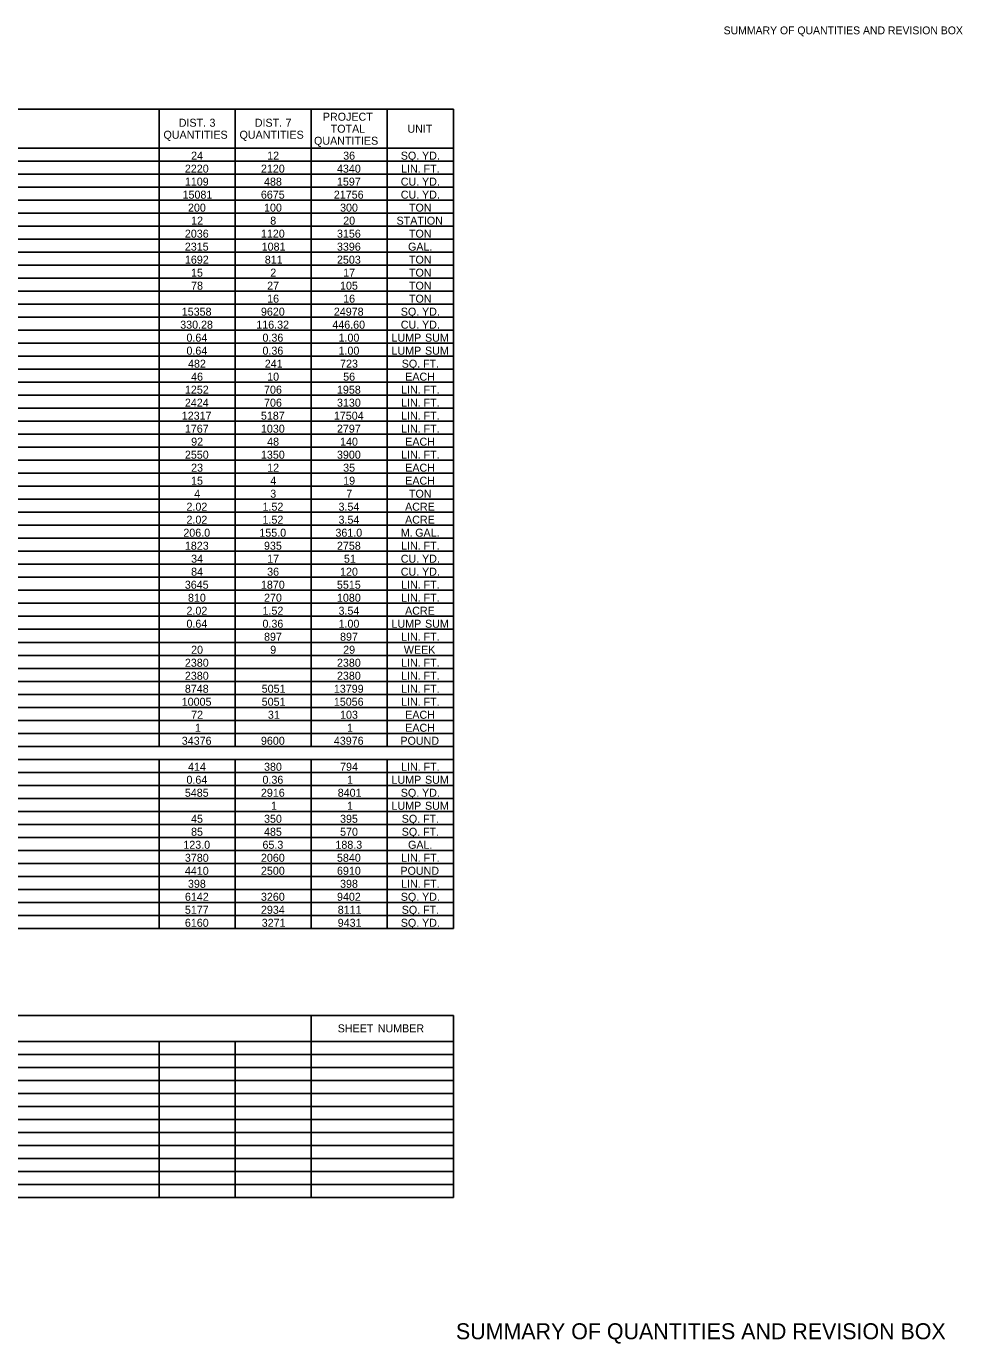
# Model space of a CAD drawing. Extents: x 544478 to 1930787, y -1948294 to 596640.
# Drawn here: x 546965 to 547668, y -1948294 to -1947306 of the extents above; entities that cross this region are included whole.
import ezdxf

# ---------------------------------------------------------------- set-up
doc = ezdxf.new("R2010")
doc.units = 0
for name, color, linetype in [('Default', 7, 'Continuous'), ('R_Border', 7, 'Continuous'), ('R_Border Prem', 7, 'Continuous')]:
    doc.layers.add(name, color=color, linetype=linetype)

msp = doc.modelspace()

# ---------------------------------------------------------------- linework, layer by layer
at = {"layer": 'Default'}
for p, q in [((546495.1, -1947368.6), (547285.83, -1947368.6)), ((547064.99, -1947846.35), (547064.99, -1947368.6)), ((547064.99, -1947719.6), (547064.99, -1947368.6)), ((547122.03, -1947846.35), (547122.03, -1947368.6)), ((547122.03, -1947397.85), (547122.03, -1947368.6)), ((547179.06, -1947846.35), (547179.06, -1947368.6)), ((547236.1, -1947846.35), (547236.1, -1947368.6)), ((547236.1, -1947846.35), (547236.1, -1947368.6)), ((547285.83, -1947982.85), (547285.83, -1947368.6)), ((546495.1, -1947397.85), (547285.83, -1947397.85)), ((546495.1, -1947397.85), (547285.83, -1947397.85)), ((546495.1, -1947407.6), (547285.83, -1947407.6)), ((546495.1, -1947417.35), (547285.83, -1947417.35)), ((546495.1, -1947427.1), (547285.83, -1947427.1)), ((546495.1, -1947436.85), (547285.83, -1947436.85)), ((546495.1, -1947446.6), (547285.83, -1947446.6)), ((546495.1, -1947456.35), (547285.83, -1947456.35)), ((546495.1, -1947466.1), (547285.83, -1947466.1)), ((546495.1, -1947475.85), (547285.83, -1947475.85)), ((546495.1, -1947485.6), (547285.83, -1947485.6)), ((546495.1, -1947495.35), (547285.83, -1947495.35)), ((546495.1, -1947505.1), (547285.83, -1947505.1)), ((546495.1, -1947514.85), (547285.83, -1947514.85)), ((546495.1, -1947524.6), (547285.83, -1947524.6)), ((546495.1, -1947534.35), (547285.83, -1947534.35)), ((546495.1, -1947544.1), (547285.83, -1947544.1)), ((546495.1, -1947553.85), (547285.83, -1947553.85)), ((546495.1, -1947563.6), (547285.83, -1947563.6)), ((546495.1, -1947573.35), (547285.83, -1947573.35)), ((546495.1, -1947583.1), (547285.83, -1947583.1)), ((546495.1, -1947592.85), (547285.83, -1947592.85)), ((546495.1, -1947602.6), (547285.83, -1947602.6)), ((546495.1, -1947612.35), (547285.83, -1947612.35)), ((546495.1, -1947622.1), (547285.83, -1947622.1)), ((546495.1, -1947631.85), (547285.83, -1947631.85)), ((546495.1, -1947641.6), (547285.83, -1947641.6)), ((546495.1, -1947651.35), (547285.83, -1947651.35)), ((546495.1, -1947661.1), (547285.83, -1947661.1)), ((546495.1, -1947670.85), (547285.83, -1947670.85)), ((546495.1, -1947680.6), (547285.83, -1947680.6)), ((546495.1, -1947690.35), (547285.83, -1947690.35)), ((546495.1, -1947700.1), (547285.83, -1947700.1)), ((546495.1, -1947709.85), (547285.83, -1947709.85)), ((546495.1, -1947719.6), (547285.83, -1947719.6)), ((546495.1, -1947729.35), (547285.83, -1947729.35)), ((547064.99, -1947846.35), (547064.99, -1947729.35)), ((547236.1, -1947729.35), (547285.83, -1947729.35)), ((546495.1, -1947739.1), (547285.83, -1947739.1)), ((546495.1, -1947748.85), (547285.83, -1947748.85)), ((546495.1, -1947758.6), (547285.83, -1947758.6)), ((546495.1, -1947768.35), (547285.83, -1947768.35)), ((546495.1, -1947778.1), (547285.83, -1947778.1)), ((546977.24, -1947778.1), (547064.99, -1947778.1)), ((547064.99, -1947778.1), (547285.83, -1947778.1)), ((546495.1, -1947787.85), (547285.83, -1947787.85)), ((546495.1, -1947797.6), (547285.83, -1947797.6)), ((546495.1, -1947807.35), (547285.83, -1947807.35)), ((546495.1, -1947817.1), (547285.83, -1947817.1)), ((546495.1, -1947826.85), (547285.83, -1947826.85)), ((546495.1, -1947836.6), (547285.83, -1947836.6)), ((546495.1, -1947846.35), (547285.83, -1947846.35)), ((546495.1, -1947846.35), (547285.83, -1947846.35)), ((546495.1, -1947856.1), (547285.83, -1947856.1)), ((546495.1, -1947856.1), (547122.03, -1947856.1)), ((547064.99, -1947982.85), (547064.99, -1947856.1)), ((547064.99, -1947982.85), (547064.99, -1947856.1)), ((547122.03, -1947982.85), (547122.03, -1947856.1)), ((547179.06, -1947856.1), (547285.83, -1947856.1)), ((547179.06, -1947982.85), (547179.06, -1947856.1)), ((547236.1, -1947982.85), (547236.1, -1947856.1)), ((547236.1, -1947982.85), (547236.1, -1947856.1)), ((546495.1, -1947865.85), (547285.83, -1947865.85)), ((546495.1, -1947875.6), (547285.83, -1947875.6)), ((546495.1, -1947885.35), (547285.83, -1947885.35)), ((546495.1, -1947895.1), (547285.83, -1947895.1)), ((546495.1, -1947904.85), (547285.83, -1947904.85)), ((546495.1, -1947914.6), (547285.83, -1947914.6)), ((546495.1, -1947924.35), (547285.83, -1947924.35)), ((546495.1, -1947934.1), (547285.83, -1947934.1)), ((546495.1, -1947943.85), (547285.83, -1947943.85)), ((546495.1, -1947953.6), (547285.83, -1947953.6)), ((546977.24, -1947953.6), (547064.99, -1947953.6)), ((547064.99, -1947953.6), (547285.83, -1947953.6)), ((546495.1, -1947963.35), (547285.83, -1947963.35)), ((546977.24, -1947963.35), (547064.99, -1947963.35)), ((547064.99, -1947963.35), (547285.83, -1947963.35)), ((546495.1, -1947973.1), (547285.83, -1947973.1)), ((546977.24, -1947973.1), (547064.99, -1947973.1)), ((547064.99, -1947973.1), (547285.83, -1947973.1)), ((546495.1, -1947982.85), (547285.83, -1947982.85)), ((546495.1, -1948048.06), (547285.83, -1948048.06)), ((547064.99, -1948048.06), (547285.83, -1948048.06)), ((547179.06, -1948067.56), (547179.06, -1948048.06)), ((547179.06, -1948184.56), (547179.06, -1948048.06)), ((547285.83, -1948184.56), (547285.83, -1948048.06)), ((546495.1, -1948067.56), (547285.83, -1948067.56)), ((547064.99, -1948184.56), (547064.99, -1948067.56)), ((547122.03, -1948184.56), (547122.03, -1948067.56)), ((547179.06, -1948067.56), (547285.83, -1948067.56)), ((546495.1, -1948077.31), (547285.83, -1948077.31)), ((546495.1, -1948087.06), (547285.83, -1948087.06)), ((546495.1, -1948096.81), (547285.83, -1948096.81)), ((546495.1, -1948106.56), (547285.83, -1948106.56)), ((546495.1, -1948116.31), (547285.83, -1948116.31)), ((546495.1, -1948126.06), (547285.83, -1948126.06)), ((546495.1, -1948135.81), (547285.83, -1948135.81)), ((546495.1, -1948145.56), (547285.83, -1948145.56)), ((546495.1, -1948155.31), (547285.83, -1948155.31)), ((546495.1, -1948165.06), (547285.83, -1948165.06)), ((546495.1, -1948174.81), (547285.83, -1948174.81)), ((546495.1, -1948184.56), (547285.83, -1948184.56))]:
    msp.add_line(p, q, dxfattribs=at)

# ---------------------------------------------------------------- texts
for s, p in [('DIST.', (547079.77, -1947381.72)), (' 3', (547100.62, -1947381.72)), ('DIST.', (547136.81, -1947381.72)), (' 7', (547157.66, -1947381.72)), ('PROJECT', (547187.87, -1947377.22)), ('QUANTITIES', (547068.33, -1947390.72)), ('QUANTITIES', (547125.37, -1947390.72)), ('TOTAL', (547193.74, -1947386.22)), ('UNIT', (547251.27, -1947386.22)), ('QUANTITIES', (547181.24, -1947395.22)), ('24', (547089.05, -1947406.4)), ('12', (547146.11, -1947406.4)), ('36', (547203.11, -1947406.4)), ('SQ.', (547246.32, -1947406.4)), (' YD.', (547260.03, -1947406.4)), ('2220', (547084.39, -1947416.15)), ('2120', (547141.43, -1947416.15)), ('4340', (547198.46, -1947416.15)), ('LIN.', (547246.56, -1947416.15)), (' FT.', (547261.2, -1947416.15)), ('1109', (547084.37, -1947425.9)), ('488', (547143.74, -1947425.9)), ('1597', (547198.45, -1947425.9)), ('CU.', (547246.33, -1947425.9)), (' YD.', (547260.03, -1947425.9)), ('15081', (547082.63, -1947435.65)), ('6675', (547141.39, -1947435.65)), ('21756', (547196.12, -1947435.65)), ('CU.', (547246.33, -1947435.65)), (' YD.', (547260.03, -1947435.65)), ('200', (547086.72, -1947445.4)), ('100', (547143.76, -1947445.4)), ('300', (547200.79, -1947445.4)), ('TON', (547252.46, -1947445.4)), ('12', (547089.07, -1947455.15)), ('8', (547148.4, -1947455.15)), ('20', (547203.12, -1947455.15)), ('STATION', (547243.14, -1947455.15)), ('2036', (547084.38, -1947464.9)), ('1120', (547141.43, -1947464.9)), ('3156', (547198.45, -1947464.9)), ('TON', (547252.46, -1947464.9)), ('2315', (547084.35, -1947474.65)), ('1081', (547142, -1947474.65)), ('3396', (547198.45, -1947474.65)), ('GAL.', (547251.78, -1947474.65)), ('1692', (547084.41, -1947484.4)), ('811', (547144.33, -1947484.4)), ('2503', (547198.45, -1947484.4)), ('TON', (547252.46, -1947484.4)), ('15', (547089.01, -1947494.15)), ('2', (547148.44, -1947494.15)), ('17', (547203.11, -1947494.15)), ('TON', (547252.46, -1947494.15)), ('78', (547089.03, -1947503.9)), ('27', (547146.08, -1947503.9)), ('105', (547200.76, -1947503.9)), ('TON', (547252.46, -1947503.9)), ('16', (547146.08, -1947513.65)), ('16', (547203.11, -1947513.65)), ('TON', (547252.46, -1947513.65)), ('15358', (547082.04, -1947523.4)), ('9620', (547141.43, -1947523.4)), ('24978', (547196.12, -1947523.4)), ('SQ.', (547246.32, -1947523.4)), (' YD.', (547260.03, -1947523.4)), ('330.28', (547080.88, -1947533.15)), ('116.32', (547137.95, -1947533.15)), ('446.60', (547194.97, -1947533.15)), ('CU.', (547246.33, -1947533.15)), (' YD.', (547260.03, -1947533.15)), ('0.64', (547085.56, -1947542.9)), ('0.36', (547142.58, -1947542.9)), ('1.00', (547199.63, -1947542.9)), ('LUMP', (547239.34, -1947542.9)), (' SUM', (547262.26, -1947542.9)), ('0.64', (547085.56, -1947552.65)), ('0.36', (547142.58, -1947552.65)), ('1.00', (547199.63, -1947552.65)), ('LUMP', (547239.34, -1947552.65)), (' SUM', (547262.26, -1947552.65)), ('482', (547086.74, -1947562.4)), ('241', (547144.33, -1947562.4)), ('723', (547200.78, -1947562.4)), ('SQ.', (547247.03, -1947562.4)), (' FT.', (547260.74, -1947562.4)), ('1252', (547084.41, -1947581.9)), ('46', (547089.04, -1947572.15)), ('706', (547143.75, -1947581.9)), ('10', (547146.09, -1947572.15)), ('1958', (547198.45, -1947581.9)), ('56', (547203.11, -1947572.15)), ('EACH', (547249.65, -1947572.15)), ('2424', (547084.39, -1947591.65)), ('706', (547143.75, -1947591.65)), ('3130', (547198.46, -1947591.65)), ('LIN.', (547246.56, -1947581.9)), ('LIN.', (547246.56, -1947591.65)), (' FT.', (547261.2, -1947581.9)), (' FT.', (547261.2, -1947591.65)), ('12317', (547082.05, -1947601.4)), ('5187', (547141.42, -1947601.4)), ('17504', (547196.14, -1947601.4)), ('LIN.', (547246.56, -1947601.4)), (' FT.', (547261.2, -1947601.4)), ('1767', (547084.38, -1947611.15)), ('1030', (547141.43, -1947611.15)), ('2797', (547198.45, -1947611.15)), ('LIN.', (547246.56, -1947611.15)), (' FT.', (547261.2, -1947611.15)), ('92', (547089.07, -1947620.9)), ('48', (547146.07, -1947620.9)), ('140', (547200.79, -1947620.9)), ('EACH', (547249.65, -1947620.9)), ('2550', (547084.39, -1947630.65)), ('1350', (547141.43, -1947630.65)), ('3900', (547198.46, -1947630.65)), ('LIN.', (547246.56, -1947630.65)), (' FT.', (547261.2, -1947630.65)), ('23', (547089.04, -1947640.4)), ('12', (547146.11, -1947640.4)), ('35', (547203.09, -1947640.4)), ('EACH', (547249.65, -1947640.4)), ('15', (547089.01, -1947650.15)), ('4', (547148.42, -1947650.15)), ('19', (547203.11, -1947650.15)), ('EACH', (547249.65, -1947650.15)), ('4', (547091.38, -1947659.9)), ('3', (547148.41, -1947659.9)), ('7', (547205.44, -1947659.9)), ('TON', (547252.46, -1947659.9)), ('2.02', (547085.58, -1947669.65)), ('1.52', (547142.61, -1947669.65)), ('3.54', (547199.63, -1947669.65)), ('ACRE', (547249.54, -1947669.65)), ('2.02', (547085.58, -1947679.4)), ('1.52', (547142.61, -1947679.4)), ('3.54', (547199.63, -1947679.4)), ('ACRE', (547249.54, -1947679.4)), ('206.0', (547083.23, -1947689.15)), ('155.0', (547140.26, -1947689.15)), ('361.0', (547197.3, -1947689.15)), ('M.', (547246.33, -1947689.15)), (' GAL.', (547254.9, -1947689.15)), ('1823', (547084.38, -1947698.9)), ('935', (547143.72, -1947698.9)), ('2758', (547198.45, -1947698.9)), ('LIN.', (547246.56, -1947698.9)), (' FT.', (547261.2, -1947698.9)), ('34', (547089.05, -1947708.65)), ('17', (547146.08, -1947708.65)), ('51', (547203.69, -1947708.65)), ('CU.', (547246.33, -1947708.65)), (' YD.', (547260.03, -1947708.65)), ('84', (547089.05, -1947718.4)), ('36', (547146.08, -1947718.4)), ('120', (547200.79, -1947718.4)), ('CU.', (547246.33, -1947718.4)), (' YD.', (547260.03, -1947718.4)), ('3645', (547084.35, -1947728.15)), ('1870', (547141.43, -1947728.15)), ('5515', (547198.43, -1947728.15)), ('LIN.', (547246.56, -1947728.15)), (' FT.', (547261.2, -1947728.15)), ('810', (547086.72, -1947737.9)), ('270', (547143.76, -1947737.9)), ('1080', (547198.46, -1947737.9)), ('LIN.', (547246.56, -1947737.9)), (' FT.', (547261.2, -1947737.9)), ('2.02', (547085.58, -1947747.65)), ('1.52', (547142.61, -1947747.65)), ('3.54', (547199.63, -1947747.65)), ('ACRE', (547249.54, -1947747.65)), ('0.64', (547085.56, -1947757.4)), ('0.36', (547142.58, -1947757.4)), ('1.00', (547199.63, -1947757.4)), ('LUMP', (547239.34, -1947757.4)), (' SUM', (547262.26, -1947757.4)), ('897', (547143.75, -1947767.15)), ('897', (547200.78, -1947767.15)), ('LIN.', (547246.56, -1947767.15)), (' FT.', (547261.2, -1947767.15)), ('20', (547089.05, -1947776.9)), ('9', (547148.4, -1947776.9)), ('29', (547203.11, -1947776.9)), ('WEEK', (547248.63, -1947776.9)), ('2380', (547084.39, -1947786.65)), ('2380', (547198.46, -1947786.65)), ('LIN.', (547246.56, -1947786.65)), (' FT.', (547261.2, -1947786.65)), ('2380', (547084.39, -1947796.4)), ('2380', (547198.46, -1947796.4)), ('LIN.', (547246.56, -1947796.4)), (' FT.', (547261.2, -1947796.4)), ('8748', (547084.37, -1947806.15)), ('5051', (547142, -1947806.15)), ('13799', (547196.12, -1947806.15)), ('LIN.', (547246.56, -1947806.15)), (' FT.', (547261.2, -1947806.15)), ('10005', (547082.02, -1947815.9)), ('5051', (547142, -1947815.9)), ('15056', (547196.12, -1947815.9)), ('LIN.', (547246.56, -1947815.9)), (' FT.', (547261.2, -1947815.9)), ('72', (547089.07, -1947825.65)), ('31', (547146.66, -1947825.65)), ('103', (547200.78, -1947825.65)), ('EACH', (547249.65, -1947825.65)), ('1', (547091.95, -1947835.4)), ('1', (547206.02, -1947835.4)), ('EACH', (547249.65, -1947835.4)), ('34376', (547082.05, -1947845.15)), ('9600', (547141.43, -1947845.15)), ('43976', (547196.12, -1947845.15)), ('POUND', (547246.05, -1947845.15)), ('414', (547086.72, -1947864.65)), ('380', (547143.76, -1947864.65)), ('794', (547200.8, -1947864.65)), ('LIN.', (547246.56, -1947864.65)), (' FT.', (547261.2, -1947864.65)), ('0.64', (547085.56, -1947874.4)), ('0.36', (547142.58, -1947874.4)), ('1', (547206.02, -1947874.4)), ('LUMP', (547239.34, -1947874.4)), (' SUM', (547262.26, -1947874.4)), ('5485', (547084.35, -1947884.15)), ('2916', (547141.42, -1947884.15)), ('8401', (547199.03, -1947884.15)), ('SQ.', (547246.32, -1947884.15)), (' YD.', (547260.03, -1947884.15)), ('1', (547148.99, -1947893.9)), ('1', (547206.02, -1947893.9)), ('LUMP', (547239.34, -1947893.9)), (' SUM', (547262.26, -1947893.9)), ('45', (547089.01, -1947903.65)), ('350', (547143.76, -1947903.65)), ('395', (547200.76, -1947903.65)), ('SQ.', (547247.03, -1947903.65)), (' FT.', (547260.74, -1947903.65)), ('85', (547089.01, -1947913.4)), ('485', (547143.72, -1947913.4)), ('570', (547200.79, -1947913.4)), ('SQ.', (547247.03, -1947913.4)), (' FT.', (547260.74, -1947913.4)), ('123.0', (547083.23, -1947923.15)), ('65.3', (547142.58, -1947923.15)), ('188.3', (547197.29, -1947923.15)), ('GAL.', (547251.78, -1947923.15)), ('3780', (547084.39, -1947932.9)), ('2060', (547141.43, -1947932.9)), ('5840', (547198.46, -1947932.9)), ('LIN.', (547246.56, -1947932.9)), (' FT.', (547261.2, -1947932.9)), ('4410', (547084.39, -1947942.65)), ('2500', (547141.43, -1947942.65)), ('6910', (547198.46, -1947942.65)), ('POUND', (547246.05, -1947942.65)), ('398', (547086.7, -1947952.4)), ('398', (547200.78, -1947952.4)), ('LIN.', (547246.56, -1947952.4)), (' FT.', (547261.2, -1947952.4)), ('6142', (547084.41, -1947962.15)), ('3260', (547141.43, -1947962.15)), ('9402', (547198.48, -1947962.15)), ('SQ.', (547246.32, -1947962.15)), (' YD.', (547260.03, -1947962.15)), ('5177', (547084.38, -1947971.9)), ('2934', (547141.43, -1947971.9)), ('8111', (547199.03, -1947971.9)), ('SQ.', (547247.03, -1947971.9)), (' FT.', (547260.74, -1947971.9)), ('6160', (547084.39, -1947981.65)), ('3271', (547142, -1947981.65)), ('9431', (547199.03, -1947981.65)), ('SQ.', (547246.32, -1947981.65)), (' YD.', (547260.03, -1947981.65)), ('SHEET', (547199.01, -1948060.81)), (' NUMBER', (547226.8, -1948060.81))]:
    msp.add_text(s, height=6, dxfattribs=at).set_placement(p)
at = {"layer": 'R_Border'}
msp.add_text('SUMMARY OF QUANTITIES AND REVISION BOX', height=12, rotation=360, dxfattribs=at).set_placement((547287.69, -1948290.95))
at = {"layer": 'R_Border Prem'}
msp.add_text('SUMMARY OF QUANTITIES AND REVISION BOX', height=5.862, rotation=360, dxfattribs=at).set_placement((547488.49, -1947312.39))

doc.saveas('drawing.dxf')
